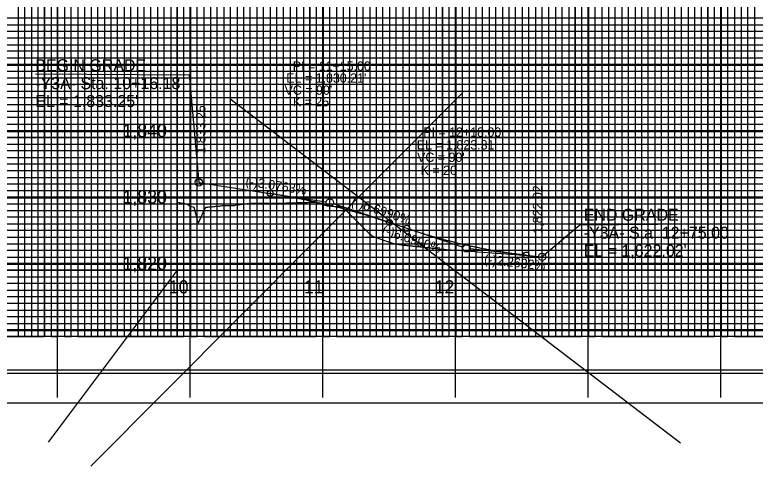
# Model space of a CAD drawing. Extents: x 553912 to 567693, y 512355 to 537539.
# Drawn here: x 560417 to 560975, y 521003 to 521343 of the extents above; entities that cross this region are included whole.
import ezdxf

# ---------------------------------------------------------------- set-up
doc = ezdxf.new("R2010")
doc.units = 0
for name, color, linetype in [('Default', 7, 'Continuous'), ('Exist Vertical Profile Ground Line', 7, 'Continuous'), ('Exist Vertical Profile Horizontal Axis Label Major', 7, 'Continuous'), ('Exist Vertical Profile Vertical Axis Label', 7, 'Continuous'), ('Old_Level_42', 7, 'Continuous'), ('Old_Level_51', 7, 'Continuous'), ('Old_Level_53', 7, 'Continuous'), ('Old_Level_54', 7, 'Continuous'), ('Prop ROW Permanent Easement CELL', 7, 'Continuous'), ('Prop Vertical Profile Curve Label', 7, 'Continuous'), ('Prop Vertical Profile Grade', 7, 'Continuous'), ('Prop Vertical Profile Grade Label', 7, 'Continuous'), ('Prop VPI Label', 7, 'Continuous'), ('Sheet Profile Grid Major CELL', 7, 'Continuous'), ('Sheet Row Area Data CELL', 7, 'Continuous'), ('Sheet Summary Guardrail CELL', 7, 'Continuous')]:
    doc.layers.add(name, color=color, linetype=linetype)

msp = doc.modelspace()

# ---------------------------------------------------------------- linework, layer by layer
at = {"layer": 'Default'}
msp.add_lwpolyline([(561456.66, 522150.42), (559772.66, 522150.42), (559772.66, 521050.42), (561456.66, 521050.42)], close=True, dxfattribs=at)
at = {"layer": 'Exist Vertical Profile Ground Line'}
for points in [[(560539.66, 521201.76), (560545.51, 521200.67), (560546.99, 521200.43), (560548.85, 521198.92), (560552.01, 521198.01), (560554.97, 521187.43), (560555.59, 521186.29), (560560.34, 521196.62), (560560.69, 521197.08), (560561.38, 521197.92), (560561.81, 521197.97), (560562.58, 521198.06), (560563.35, 521198.14), (560564.12, 521198.21), (560564.9, 521198.28), (560565.67, 521198.35), (560566.44, 521198.42), (560567.21, 521198.48), (560567.98, 521198.55), (560568.76, 521198.61), (560569.53, 521198.68), (560570.3, 521198.74), (560571.33, 521198.82), (560571.84, 521198.91), (560572.62, 521199.04), (560573.39, 521199.17), (560573.77, 521199.24), (560574.16, 521199.24), (560574.93, 521199.25), (560575.7, 521199.26), (560576.47, 521199.27), (560577.25, 521199.28), (560578.02, 521199.29), (560578.79, 521199.29), (560579.56, 521199.3), (560579.96, 521199.3), (560580.33, 521199.3), (560581.11, 521199.3), (560581.88, 521199.3), (560582.18, 521199.29), (560582.65, 521199.32), (560583.42, 521199.5), (560584.19, 521199.61), (560584.96, 521199.71), (560585.74, 521199.82), (560586.51, 521199.92), (560587.28, 521200.02), (560588.05, 521200.12), (560588.82, 521200.22), (560589.6, 521200.32), (560590.37, 521200.42), (560591.14, 521200.51), (560591.91, 521200.6), (560592.68, 521200.7), (560593.46, 521200.79), (560594.23, 521200.87), (560595, 521200.96), (560596.05, 521201.07), (560596.54, 521201.07), (560597.31, 521201.07), (560598.09, 521201.07), (560598.86, 521201.07), (560599.63, 521201.06), (560600.4, 521201.06), (560601.17, 521201.06), (560601.95, 521201.05), (560602.97, 521201.05), (560603.49, 521201.05), (560604.26, 521201.05), (560605.03, 521201.04), (560605.81, 521201.04), (560606.58, 521201.04), (560607.35, 521201.04), (560608.12, 521201.04), (560608.89, 521201.04), (560609.66, 521201.03), (560610.44, 521201.03), (560611.21, 521201.03), (560611.98, 521201.03), (560612.75, 521201.02), (560613.52, 521201.02), (560614.3, 521201.01), (560615.07, 521201.01), (560615.84, 521201.01), (560616.61, 521201), (560617.08, 521201), (560617.38, 521200.98), (560618.16, 521200.94), (560618.93, 521200.92), (560619.95, 521200.98), (560620.47, 521201.03), (560621.24, 521201.09), (560622.01, 521201.15), (560622.35, 521201.17), (560622.79, 521201.19), (560623.56, 521201.21), (560624.33, 521201.23), (560625.1, 521201.26), (560625.87, 521201.28), (560626.65, 521201.3), (560627.42, 521201.32)], [(560627.42, 521201.32), (560628.19, 521201.34), (560628.96, 521201.35), (560629.73, 521201.37), (560630.51, 521201.38), (560631.28, 521201.4), (560632.05, 521201.41), (560632.82, 521201.42), (560633.61, 521201.43), (560634.36, 521201.47), (560635.14, 521201.51), (560635.91, 521201.54), (560636.68, 521201.57), (560637.45, 521201.61), (560638.22, 521201.64), (560643.79, 521201.86), (560644.47, 521201.68), (560644.86, 521201.57), (560652.49, 521199.1), (560655.82, 521198.8), (560662.13, 521198.51), (560664.08, 521198.03), (560664.41, 521198), (560684.15, 521178.24), (560687.28, 521175.86), (560690.9, 521174.53), (560696.7, 521172.57), (560697.59, 521172.27), (560698.48, 521171.98), (560699.38, 521171.69), (560700.27, 521171.41), (560701.16, 521171.13), (560702.06, 521170.86), (560702.95, 521170.59), (560703.85, 521170.33), (560704.27, 521170.21), (560704.74, 521170.15), (560705.63, 521170.03), (560706.53, 521169.91), (560707.42, 521169.8), (560708.31, 521169.68), (560709.21, 521169.57), (560710.1, 521169.46), (560710.99, 521169.34), (560711.89, 521169.23), (560712.78, 521169.13), (560713.67, 521169.04), (560714.57, 521168.96), (560715.46, 521168.88), (560716.35, 521168.8), (560717.25, 521168.71), (560718.14, 521168.63), (560719.04, 521168.54), (560719.93, 521168.46), (560720.82, 521168.36), (560721.72, 521168.26), (560722.61, 521168.17), (560723.5, 521168.07), (560724.4, 521167.97), (560725.29, 521167.87), (560726.18, 521167.77), (560727.08, 521167.67), (560727.97, 521167.57), (560728.86, 521167.47), (560729.76, 521167.37), (560730.65, 521167.27), (560731.54, 521167.17), (560732.44, 521167.07), (560733.33, 521166.97), (560734.22, 521166.87), (560735.12, 521166.77), (560736.01, 521166.67), (560736.91, 521166.57), (560737.8, 521166.47), (560738.69, 521166.37), (560739.12, 521166.32), (560739.59, 521166.29), (560740.48, 521166.23), (560741.37, 521166.17), (560742.27, 521166.11), (560764.19, 521164.52), (560765.99, 521164.41), (560794.51, 521162.29), (560820.15, 521160.03), (560821.4, 521159.94)]]:
    msp.add_lwpolyline(points, dxfattribs=at)
at = {"layer": 'Old_Level_42'}
for p, q in [((560439.66, 522125.42), (560439.66, 521100.42)), ((560489.66, 522125.42), (560489.66, 521100.42)), ((560539.66, 522125.42), (560539.66, 521100.42)), ((560589.66, 522125.42), (560589.66, 521100.42)), ((560639.66, 522125.42), (560639.66, 521100.42)), ((560689.66, 522125.42), (560689.66, 521100.42)), ((560739.66, 522125.42), (560739.66, 521100.42)), ((560789.66, 522125.42), (560789.66, 521100.42)), ((560839.66, 522125.42), (560839.66, 521100.42)), ((560889.66, 522125.42), (560889.66, 521100.42)), ((560939.66, 522125.42), (560939.66, 521100.42)), ((559939.66, 521300.42), (561439.66, 521300.42)), ((559939.66, 521250.42), (561439.66, 521250.42)), ((559939.66, 521200.42), (561439.66, 521200.42)), ((559939.66, 521150.42), (561439.66, 521150.42))]:
    msp.add_line(p, q, dxfattribs=at)
at = {"layer": 'Old_Level_51'}
msp.add_lwpolyline([(561452.16, 522127.97), (559785.66, 522127.97), (559785.66, 521072.87), (561452.16, 521072.87)], close=True, dxfattribs=at)
at = {"layer": 'Old_Level_53'}
msp.add_line((561439.66, 521100.42), (559939.66, 521100.42), dxfattribs=at)
msp.add_lwpolyline([(561439.66, 522125.42), (559939.66, 522125.42), (559939.66, 521075.42), (561439.66, 521075.42)], close=True, dxfattribs=at)
at = {"layer": 'Old_Level_54'}
for points in [[(560389.66, 522125.42), (560389.66, 521100.42), (560439.66, 521100.42), (560439.66, 522125.42)], [(560489.66, 522125.42), (560489.66, 521100.42), (560539.66, 521100.42), (560539.66, 522125.42)], [(560589.66, 522125.42), (560589.66, 521100.42), (560639.66, 521100.42), (560639.66, 522125.42)], [(560689.66, 522125.42), (560689.66, 521100.42), (560739.66, 521100.42), (560739.66, 522125.42)], [(560789.66, 522125.42), (560789.66, 521100.42), (560839.66, 521100.42), (560839.66, 522125.42)], [(560889.66, 522125.42), (560889.66, 521100.42), (560939.66, 521100.42), (560939.66, 522125.42)], [(561439.66, 521250.42), (559939.66, 521250.42), (559939.66, 521300.42), (561439.66, 521300.42)], [(561439.66, 521150.42), (559939.66, 521150.42), (559939.66, 521200.42), (561439.66, 521200.42)]]:
    msp.add_lwpolyline(points, dxfattribs=at)
at = {"layer": 'Prop ROW Permanent Easement CELL'}
for points in [[(560464.66, 522125.42), (560464.66, 521100.42), (560514.66, 521100.42), (560514.66, 522125.42)], [(560564.66, 522125.42), (560564.66, 521100.42), (560614.66, 521100.42), (560614.66, 522125.42)], [(560664.66, 522125.42), (560664.66, 521100.42), (560714.66, 521100.42), (560714.66, 522125.42)], [(560764.66, 522125.42), (560764.66, 521100.42), (560814.66, 521100.42), (560814.66, 522125.42)], [(560864.66, 522125.42), (560864.66, 521100.42), (560914.66, 521100.42), (560914.66, 522125.42)], [(560964.66, 522125.42), (560964.66, 521100.42), (561014.66, 521100.42)], [(561439.66, 521325.42), (559939.66, 521325.42), (559939.66, 521275.42), (561439.66, 521275.42)], [(561439.66, 521225.42), (559939.66, 521225.42), (559939.66, 521175.42), (561439.66, 521175.42)], [(561439.66, 521125.42), (559939.66, 521125.42)]]:
    msp.add_lwpolyline(points, dxfattribs=at)
at = {"layer": 'Prop Vertical Profile Curve Label'}
for centre in [(560609.66, 521208.39), (560699.66, 521186.4), (560712.66, 521182.05), (560802.66, 521161.88)]:
    msp.add_circle(centre, 2.25, dxfattribs=at)
at = {"layer": 'Prop Vertical Profile Grade'}
for p, q in [((560555.84, 521216.67), (560609.66, 521208.39)), ((560699.66, 521186.4), (560712.66, 521182.05)), ((560802.66, 521161.88), (560814.66, 521160.52))]:
    msp.add_line(p, q, dxfattribs=at)
for points in [[(560609.66, 521208.39), (560611.46, 521208.11), (560613.26, 521207.83), (560615.06, 521207.53), (560616.86, 521207.24), (560618.66, 521206.93), (560620.46, 521206.62), (560622.26, 521206.3), (560624.06, 521205.97), (560625.86, 521205.64), (560627.66, 521205.3), (560629.46, 521204.95), (560631.26, 521204.6), (560633.06, 521204.24), (560634.86, 521203.88), (560636.66, 521203.51), (560638.46, 521203.13), (560640.26, 521202.75), (560642.06, 521202.35), (560643.86, 521201.96), (560645.66, 521201.55), (560647.46, 521201.14), (560649.26, 521200.73), (560651.06, 521200.3), (560652.86, 521199.87), (560654.66, 521199.44), (560656.46, 521198.99), (560658.26, 521198.54), (560660.06, 521198.09), (560661.86, 521197.62), (560663.66, 521197.15), (560665.46, 521196.68), (560667.26, 521196.2), (560669.06, 521195.71), (560670.86, 521195.21), (560672.66, 521194.71), (560674.46, 521194.2), (560676.26, 521193.69), (560678.06, 521193.17), (560679.86, 521192.64), (560681.66, 521192.1), (560683.46, 521191.56), (560685.26, 521191.01), (560687.06, 521190.46), (560688.86, 521189.9), (560690.66, 521189.33), (560692.46, 521188.76), (560694.26, 521188.18), (560696.06, 521187.59), (560697.86, 521187), (560699.66, 521186.4)], [(560712.66, 521182.05), (560714.46, 521181.45), (560716.26, 521180.86), (560718.06, 521180.27), (560719.86, 521179.7), (560721.66, 521179.13), (560723.46, 521178.57), (560725.26, 521178.02), (560727.06, 521177.48), (560728.86, 521176.94), (560730.66, 521176.42), (560732.46, 521175.9), (560734.26, 521175.39), (560736.06, 521174.88), (560737.86, 521174.39), (560739.66, 521173.9), (560741.46, 521173.42), (560743.26, 521172.95), (560745.06, 521172.49), (560746.86, 521172.03), (560748.66, 521171.58), (560750.46, 521171.15), (560752.26, 521170.71), (560754.06, 521170.29), (560755.86, 521169.88), (560757.66, 521169.47), (560759.46, 521169.07), (560761.26, 521168.68), (560763.06, 521168.29), (560764.86, 521167.92), (560766.66, 521167.55), (560768.46, 521167.19), (560770.26, 521166.84), (560772.06, 521166.5), (560773.86, 521166.16), (560775.66, 521165.83), (560777.46, 521165.52), (560779.26, 521165.2), (560781.06, 521164.9), (560782.86, 521164.6), (560784.66, 521164.32), (560786.46, 521164.04), (560788.26, 521163.77), (560790.06, 521163.5), (560791.86, 521163.25), (560793.66, 521163), (560795.46, 521162.76), (560797.26, 521162.53), (560799.06, 521162.3), (560800.86, 521162.09), (560802.66, 521161.88)]]:
    msp.add_spline(points, degree=3, dxfattribs=at)
at = {"layer": 'Prop VPI Label'}
for p, q in [((560432.72, 521298.42), (560548.53, 521297.66)), ((560548.53, 521297.66), (560555.84, 521216.67)), ((560474.54, 521002.79), (560754.84, 521284.28)), ((560579.18, 521279.91), (560919.06, 521020.42)), ((560609.66, 521208.39), (560651.94, 521201.89)), ((560699.66, 521186.4), (560657.27, 521200.6)), ((560712.66, 521182.05), (560755.05, 521167.85)), ((560843.02, 521184.45), (560814.72, 521160.64)), ((560960.86, 521185.46), (560843.02, 521184.45)), ((560802.66, 521161.88), (560760.39, 521166.66)), ((560539.66, 521150.42), (560442.3, 521020.79))]:
    msp.add_line(p, q, dxfattribs=at)
for centre in [(560555.84, 521216.67), (560654.66, 521201.47), (560757.66, 521166.97), (560814.66, 521160.52)]:
    msp.add_circle(centre, 2.75, dxfattribs=at)
at = {"layer": 'Sheet Profile Grid Major CELL'}
for p, q in [((560449.45, 521054.67), (560449.45, 522254.67)), ((560549.45, 521054.67), (560549.45, 522254.67)), ((560649.45, 521054.67), (560649.45, 522254.67)), ((560749.45, 521054.67), (560749.45, 522254.67)), ((560849.45, 521054.67), (560849.45, 522254.67)), ((560949.45, 521054.67), (560949.45, 522254.67)), ((563849.45, 521304.67), (557249.45, 521304.67)), ((563849.45, 521254.67), (557249.45, 521254.67)), ((563849.45, 521204.67), (557249.45, 521204.67)), ((563849.45, 521154.67), (557249.45, 521154.67)), ((563849.45, 521104.67), (557249.45, 521104.67))]:
    msp.add_line(p, q, dxfattribs=at)
at = {"layer": 'Sheet Row Area Data CELL'}
msp.add_line((559772.66, 521050.42), (561456.66, 521050.42), dxfattribs=at)
at = {"layer": 'Sheet Summary Guardrail CELL'}
for points in [[(560419.66, 522125.42), (560419.66, 521100.42), (560424.66, 521100.42), (560424.66, 522125.42)], [(560429.66, 522125.42), (560429.66, 521100.42), (560434.66, 521100.42), (560434.66, 522125.42)], [(560444.66, 522125.42), (560444.66, 521100.42), (560449.66, 521100.42), (560449.66, 522125.42)], [(560454.66, 522125.42), (560454.66, 521100.42), (560459.66, 521100.42), (560459.66, 522125.42)], [(560469.66, 522125.42), (560469.66, 521100.42)], [(560474.66, 522125.42), (560474.66, 521100.42), (560479.66, 521100.42), (560479.66, 522125.42), (560484.66, 522125.42), (560484.66, 521100.42), (560494.66, 521100.42), (560494.66, 522125.42), (560499.66, 522125.42), (560499.66, 521100.42), (560504.66, 521100.42), (560504.66, 522125.42), (560509.66, 522125.42), (560509.66, 521100.42)], [(560519.66, 521100.42), (560519.66, 522125.42)], [(560524.66, 522125.42), (560524.66, 521100.42), (560529.66, 521100.42), (560529.66, 522125.42)], [(560534.66, 522125.42), (560534.66, 521100.42), (560544.66, 521100.42), (560544.66, 522125.42)], [(560549.66, 522125.42), (560549.66, 521100.42), (560549.66, 521100.42), (560554.66, 521100.42), (560554.66, 522125.42)], [(560559.66, 522125.42), (560559.66, 521100.42), (560569.66, 521100.42), (560569.66, 522125.42)], [(560574.66, 522125.42), (560574.66, 521100.42), (560579.66, 521100.42), (560579.66, 522125.42)], [(560584.66, 522125.42), (560584.66, 521100.42), (560594.66, 521100.42), (560594.66, 522125.42)], [(560599.66, 522125.42), (560599.66, 521100.42), (560604.66, 521100.42), (560604.66, 522125.42)], [(560609.66, 522125.42), (560609.66, 521100.42), (560619.66, 521100.42), (560619.66, 522125.42)], [(560624.66, 522125.42), (560624.66, 521100.42), (560629.66, 521100.42), (560629.66, 522125.42)], [(560634.66, 522125.42), (560634.66, 521100.42), (560644.66, 521100.42), (560644.66, 522125.42)], [(560649.66, 522125.42), (560649.66, 521100.42), (560654.66, 521100.42), (560654.66, 522125.42)], [(560659.66, 522125.42), (560659.66, 521100.42), (560669.66, 521100.42), (560669.66, 522125.42)], [(560674.66, 522125.42), (560674.66, 521100.42), (560679.66, 521100.42), (560679.66, 522125.42)], [(560684.66, 522125.42), (560684.66, 521100.42), (560694.66, 521100.42), (560694.66, 522125.42)], [(560699.66, 522125.42), (560699.66, 521100.42)], [(560709.66, 522124.82), (560709.66, 521100.42), (560719.66, 521100.42), (560719.66, 522125.42)], [(560724.66, 522125.42), (560724.66, 521100.42), (560729.66, 521100.42), (560729.66, 522125.42)], [(560734.66, 522125.42), (560734.66, 521100.42), (560744.66, 521100.42), (560744.66, 522125.42)], [(560749.66, 522125.42), (560749.66, 521100.42), (560754.66, 521100.42), (560754.66, 522125.42)], [(560759.66, 522125.42), (560759.66, 521100.42), (560769.66, 521100.42), (560769.66, 522125.42)], [(560774.66, 522125.42), (560774.66, 521100.42), (560779.66, 521100.42), (560779.66, 522125.42)], [(560784.66, 522125.42), (560784.66, 521100.42), (560794.66, 521100.42), (560794.66, 522125.42)], [(560799.66, 522125.42), (560799.66, 521100.42), (560804.66, 521100.42), (560804.66, 522125.42)], [(560809.66, 522125.42), (560809.66, 521100.42), (560819.66, 521100.42), (560819.66, 522125.42)], [(560824.66, 522125.42), (560824.66, 521100.42), (560829.66, 521100.42), (560829.66, 522125.42)], [(560834.66, 522125.42), (560834.66, 521100.42), (560844.66, 521100.42), (560844.66, 522125.42)], [(560849.66, 522125.42), (560849.66, 521100.42), (560854.66, 521100.42), (560854.66, 522125.42)], [(560859.66, 522125.42), (560859.66, 521100.42), (560869.66, 521100.42), (560869.66, 522125.42)], [(560874.66, 522125.42), (560874.66, 521100.42), (560879.66, 521100.42), (560879.66, 522125.42)], [(560884.66, 522125.42), (560884.66, 521100.42), (560894.66, 521100.42), (560894.66, 522125.42)], [(560899.66, 522125.42), (560899.66, 521100.42), (560904.66, 521100.42), (560904.66, 522125.42)], [(560909.66, 522125.42), (560909.66, 521100.42), (560919.66, 521100.42), (560919.66, 522125.42)], [(560924.66, 522125.42), (560924.66, 521100.42), (560929.66, 521100.42), (560929.66, 522125.42)], [(560934.66, 522125.42), (560934.66, 521100.42), (560944.66, 521100.42), (560944.66, 522125.42)], [(560949.66, 522125.42), (560949.66, 521100.42), (560954.66, 521100.42), (560954.66, 522125.42)], [(560959.66, 522125.42), (560959.66, 521100.42), (560969.66, 521100.42), (560969.66, 522125.42)], [(560974.66, 522125.42), (560974.66, 521100.42), (560979.66, 521100.42)], [(560699.66, 521100.42), (560704.66, 521100.42), (560704.66, 522124.82)], [(561389.66, 521340.42), (559989.66, 521340.42), (559989.66, 521335.42), (561389.66, 521335.42)], [(561389.66, 521330.42), (559989.66, 521330.42), (559989.66, 521320.42), (561389.66, 521320.42)], [(561389.66, 521315.42), (559989.66, 521315.42), (559989.66, 521310.42), (561389.66, 521310.42)], [(561389.66, 521305.42), (559989.66, 521305.42)], [(559989.66, 521295.42), (561389.66, 521295.42)], [(561389.66, 521290.42), (559989.66, 521290.42), (559989.66, 521285.42), (561389.66, 521285.42)], [(561389.66, 521280.42), (559989.66, 521280.42)], [(559989.66, 521270.42), (561389.66, 521270.42)], [(561389.66, 521265.42), (559989.66, 521265.42), (559989.66, 521260.42), (561389.66, 521260.42)], [(561389.66, 521255.42), (559989.66, 521255.42), (559989.66, 521245.42), (561389.66, 521245.42)], [(561389.66, 521240.42), (559989.66, 521240.42), (559989.66, 521235.42), (561389.66, 521235.42)], [(561389.66, 521230.42), (559989.66, 521230.42), (559989.66, 521220.42), (561389.66, 521220.42)], [(561389.66, 521215.42), (559989.66, 521215.42), (559989.66, 521210.42), (561389.66, 521210.42)], [(561389.66, 521205.42), (559989.66, 521205.42), (559989.66, 521195.42), (561389.66, 521195.42)], [(561389.66, 521190.42), (559989.66, 521190.42), (559989.66, 521185.42), (561389.66, 521185.42)], [(561389.66, 521180.42), (559989.66, 521180.42), (559989.66, 521170.42), (561389.66, 521170.42)], [(561389.66, 521165.42), (559989.66, 521165.42), (559989.66, 521160.42), (561389.66, 521160.42)], [(561389.66, 521155.42), (559989.66, 521155.42), (559989.66, 521145.42), (561389.66, 521145.42)], [(561389.66, 521140.42), (559989.66, 521140.42), (559989.66, 521135.42), (561389.66, 521135.42)], [(561389.66, 521130.42), (559989.66, 521130.42), (559989.66, 521120.42), (561389.66, 521120.42)], [(561389.66, 521115.42), (559989.66, 521115.42), (559989.66, 521110.42), (561389.66, 521110.42)], [(561389.66, 521105.42), (559989.66, 521105.42)]]:
    msp.add_lwpolyline(points, dxfattribs=at)

# ---------------------------------------------------------------- texts
at = {"layer": 'Exist Vertical Profile Horizontal Axis Label Major'}
for s, p in [('10', (560533.24, 521132.92)), ('12', (560733.63, 521132.92)), ('11', (560635.08, 521132.92))]:
    msp.add_text(s, height=10, dxfattribs=at).set_placement(p)
at = {"layer": 'Exist Vertical Profile Vertical Axis Label'}
for s, p in [('1,840', (560498.36, 521250.67)), ('1,830', (560498.36, 521200.67)), ('1,820', (560498.36, 521150.67))]:
    msp.add_text(s, height=10, dxfattribs=at).set_placement(p)
at = {"layer": 'Prop Vertical Profile Curve Label'}
for s, p in [("VC = 90'", (560620.53, 521282.68)), ('K = 25', (560626.76, 521273.95)), ("VC = 90'", (560720.4, 521232.09)), ('K = 20', (560723.15, 521222.27))]:
    msp.add_text(s, height=7, dxfattribs=at).set_placement(p)
at = {"layer": 'Prop Vertical Profile Grade Label'}
for s, rotation, p in [('(-)3.0763%', 351.2556, (560590.74, 521214.34)), ('(-)6.6990%', 341.4817, (560670.29, 521199.4)), ('(-)6.6990%', 341.4817, (560693.3, 521177.98)), ('(-)2.2632%', 353.544, (560770.66, 521155.44))]:
    msp.add_text(s, height=7, rotation=rotation, dxfattribs=at).set_placement(p)
at = {"layer": 'Prop VPI Label'}
for s, height, p in [('BEGIN GRADE ', 9, (560432.57, 521300.43)), ('PI = 11+15.00', 7, (560626.69, 521300.81)), ('-Y3A- Sta. 10+16.18', 9, (560432.57, 521286.93)), ("EL = 1,830.21'", 7, (560621.79, 521291.8)), ("EL = 1,833.25'", 9, (560432.57, 521273.43)), ('PI = 12+18.00', 7, (560725.06, 521251.06)), ("EL = 1,823.31'", 7, (560720.14, 521241.43)), ('END GRADE ', 9, (560846.02, 521187.73)), ('-Y3A- Sta. 12+75.00', 9, (560846.02, 521174.23)), ("EL = 1,822.02'", 9, (560846.02, 521160.73))]:
    msp.add_text(s, height=height, dxfattribs=at).set_placement(p)
for s, p in [('1,833.25', (560560.85, 521238.3)), ('1,822.02', (560814.66, 521178.02))]:
    msp.add_text(s, height=7, rotation=90, dxfattribs=at).set_placement(p)

doc.saveas('drawing.dxf')
